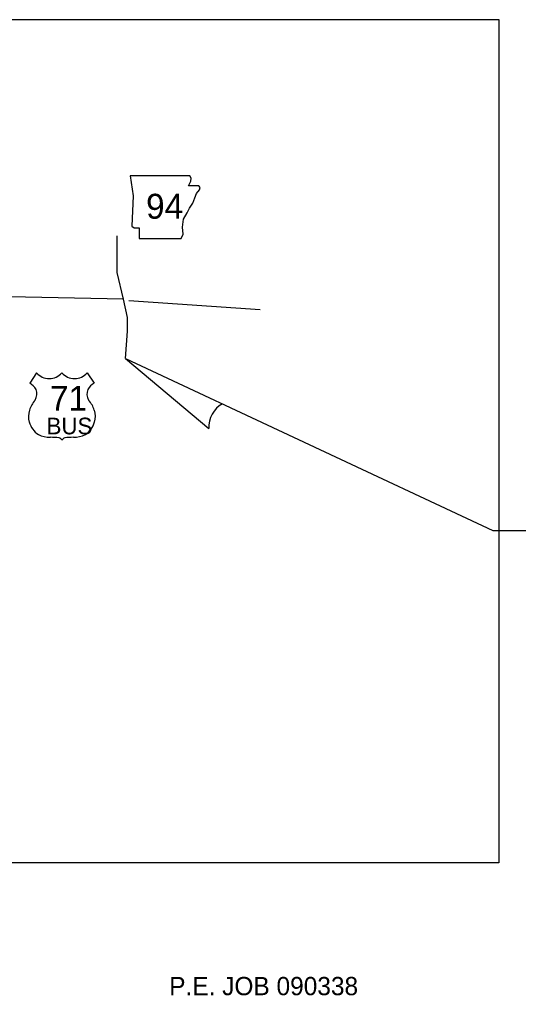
# Model space of a CAD drawing. Extents: x 309389.3 to 309420.2, y 336441.4 to 336461.2.
# Drawn here: x 309408.23 to 309413.04, y 336442.11 to 336451.5 of the extents above; entities that cross this region are included whole.
import ezdxf

# ---------------------------------------------------------------- set-up
doc = ezdxf.new("R2010")
doc.units = 0
for name, color, linetype in [('Level 3', 7, 'Continuous'), ('R_Exist Surface Annot', 7, 'Continuous'), ('R_Fin Surface', 7, 'Continuous'), ('R_MOT', 7, 'Continuous')]:
    doc.layers.add(name, color=color, linetype=linetype)

msp = doc.modelspace()

# ---------------------------------------------------------------- linework, layer by layer
at = {"layer": 'R_Exist Surface Annot'}
for p, q in [((309409.2852, 336448.7944), (309410.5483, 336448.7105)), ((309408.397, 336448.1012), (309408.3314, 336447.9998)), ((309408.8844, 336448.1012), (309408.95, 336447.9998))]:
    msp.add_line(p, q, dxfattribs=at)
msp.add_lwpolyline([(309409.2963, 336449.996), (309409.3251, 336449.8037), (309409.3123, 336449.5121), (309409.3379, 336449.4961), (309409.386, 336449.4961), (309409.386, 336449.3936), (309409.7897, 336449.3936), (309409.8089, 336449.4352), (309409.8025, 336449.5025), (309409.8121, 336449.5794), (309409.8474, 336449.6403), (309409.8698, 336449.6852), (309409.9019, 336449.7332), (309409.9211, 336449.7845), (309409.9371, 336449.8261), (309409.9659, 336449.8614), (309409.9724, 336449.8838), (309409.9595, 336449.8998), (309409.8602, 336449.8998), (309409.8826, 336449.9447), (309409.8858, 336449.9735), (309409.8726, 336449.9957)], close=True, dxfattribs=at)
for points in [[(309409.235, 336448.8079), (309409.1728, 336449.0657), (309409.1728, 336449.4191)], [(309409.2542, 336448.238), (309409.2724, 336448.5009), (309409.2724, 336448.6312), (309409.235, 336448.8079), (309398.2236, 336449.0324)]]:
    msp.add_lwpolyline(points, dxfattribs=at)
for centre, radius, start, end in [((309408.5191, 336448.2039), 0.1596, 220.07504, 319.67012), ((309408.7623, 336448.2039), 0.1596, 220.32988, 319.92496), ((309408.2457, 336447.8526), 0.1703, 30.7809, 59.98827), ((309409.0357, 336447.8526), 0.1703, 120.01173, 149.2191), ((309408.2832, 336447.8976), 0.1168, 328.81046, 21.21077), ((309408.9982, 336447.8976), 0.1168, 158.78923, 211.18954), ((309408.5886, 336447.6582), 0.2724, 138.95648, 162.69135), ((309408.6928, 336447.6582), 0.2724, 17.30865, 41.04352), ((309408.4986, 336447.6805), 0.18, 160.95764, 197.38186), ((309408.7828, 336447.6805), 0.18, 342.61814, 19.04236), ((309408.5279, 336447.6811), 0.2083, 195.10743, 237.13119), ((309408.7535, 336447.6811), 0.2083, 302.86881, 344.89257), ((309408.5318, 336447.7467), 0.2674, 244.07708, 269.57785), ((309408.7496, 336447.7467), 0.2674, 270.42215, 295.92292), ((309408.538, 336446.9894), 0.4899, 81.19416, 90.95387), ((309408.5993, 336447.4286), 0.0469, 28.03422, 72.98637), ((309408.6821, 336447.4286), 0.0469, 107.01363, 151.96578), ((309408.7434, 336446.9894), 0.4899, 89.04613, 98.80584)]:
    msp.add_arc(centre, radius, start, end, dxfattribs=at)
at = {"layer": 'R_Fin Surface'}
for p, q in [((309409.2542, 336448.238), (309412.7877, 336446.5841)), ((309409.2542, 336448.238), (309410.0553, 336447.5638)), ((309412.7877, 336446.5841), (309416.5052, 336446.5841))]:
    msp.add_line(p, q, dxfattribs=at)
msp.add_arc((309410.3047, 336447.581), 0.25, 118.13405, 183.93879, dxfattribs=at)
at = {"layer": 'R_MOT'}
msp.add_lwpolyline([(309395.4098, 336451.4994), (309412.845, 336451.4994), (309412.845, 336443.3835), (309395.4098, 336443.3835)], close=True, dxfattribs=at)

# ---------------------------------------------------------------- texts
at = {"layer": 'Level 3'}
msp.add_text('P.E. JOB 090338', height=0.175966, dxfattribs=at).set_placement((309409.6735, 336442.1113))
at = {"layer": 'R_Exist Surface Annot'}
for s, height, p in [('94', 0.24, (309409.4511, 336449.5825)), ('71', 0.24, (309408.526, 336447.7343)), ('BUS', 0.16, (309408.4935, 336447.5083))]:
    msp.add_text(s, height=height, dxfattribs=at).set_placement(p)

doc.saveas('drawing.dxf')
